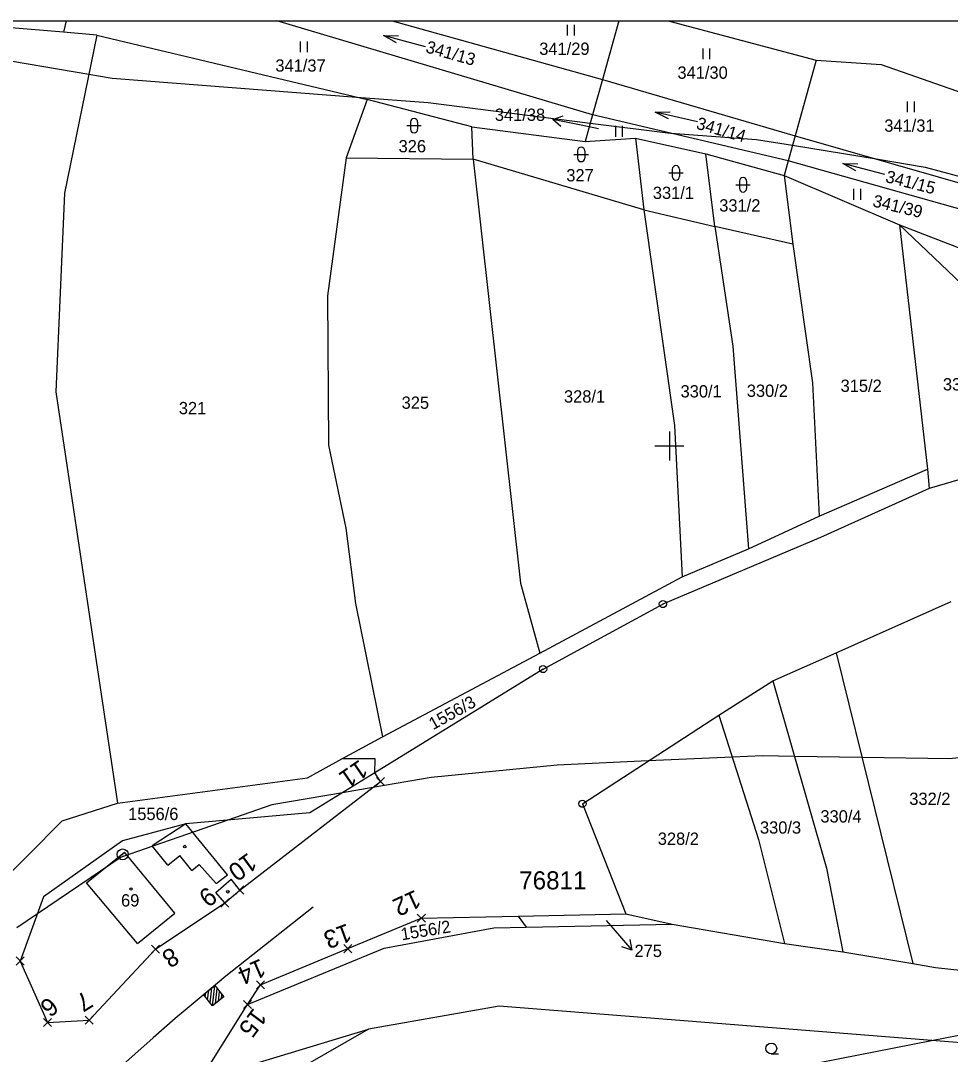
# Model space of a CAD drawing. Extents: x -756640 to -756220, y -1116031 to -1115741.
# Drawn here: x -756489.7 to -756361.1, y -1115884.2 to -1115741.2 of the extents above; entities that cross this region are included whole.
import ezdxf

# ---------------------------------------------------------------- set-up
doc = ezdxf.new("R2010")
doc.units = 0
for name, color, linetype in [('BPEJ', 7, 'Continuous'), ('GD_Starý stav', 7, 'Continuous'), ('Groma (60)', 7, 'Continuous'), ('Katastr_HRANICE DRÁHY', 7, 'Continuous'), ('Katastr_Hranice parcel', 7, 'Continuous'), ('Katastr_Parcelní čísla', 7, 'Continuous'), ('Katastr_Slučkované čáry', 7, 'Continuous'), ('Katastr_Značky kultur', 7, 'Continuous'), ('čtvercová síť', 7, 'Continuous')]:
    doc.layers.add(name, color=color, linetype=linetype)

# ---------------------------------------------------------------- blocks, each defined once
blk = doc.blocks.new('POINT_DISPLAY')
for p, q in [((-0.56, -0.56), (0.56, 0.56)), ((-0.56, 0.56), (0.56, -0.56))]:
    blk.add_line(p, q)
blk = doc.blocks.new('C691')
at = {"layer": 'čtvercová síť'}
for p, q in [((0, 0.5), (0, -0.5)), ((-0.5, 0), (0.5, 0))]:
    blk.add_line(p, q, dxfattribs=at)

msp = doc.modelspace()

# ---------------------------------------------------------------- linework, layer by layer
at = {"layer": 'BPEJ'}
for points in [[(-756499.55, -1115745.29), (-756480.27, -1115748.57), (-756477.06, -1115749.11), (-756443.26, -1115751.74), (-756433.35, -1115752.51), (-756410.94, -1115755.34), (-756399.83, -1115756.75), (-756399.8, -1115756.75), (-756387.95, -1115757.6), (-756382.96, -1115758.42), (-756371.38, -1115760.31), (-756364.61, -1115761.42), (-756355.88, -1115763.78)], [(-756355.89, -1115842.66), (-756361.22, -1115843.31), (-756373.35, -1115843.11), (-756382.69, -1115842.96), (-756387.1, -1115842.89), (-756391.28, -1115843.07), (-756402.93, -1115843.59), (-756415.53, -1115844.16), (-756432.93, -1115845.86), (-756441.01, -1115847.26), (-756445.2, -1115847.98), (-756454.99, -1115849.67), (-756461.04, -1115851.77), (-756475.79, -1115856.89), (-756487.39, -1115864.74), (-756490.21, -1115866.65)], [(-756381.59, -1115885.74), (-756363.76, -1115882.25), (-756359.95, -1115881.5), (-756342.55, -1115877.68), (-756332.79, -1115876.83)]]:
    msp.add_lwpolyline(points, dxfattribs=at)
at = {"layer": 'Defpoints'}
msp.add_line((-756640.13, -1115741.18), (-756220.13, -1115741.18), dxfattribs=at)
at = {"layer": 'GD_Starý stav'}
for p, q in [((-756449.25, -1115863.83), (-756461.35, -1115873.36)), ((-756461.35, -1115873.36), (-756463.65, -1115875.28)), ((-756463.65, -1115875.28), (-756468.32, -1115879.23)), ((-756463.52, -1115877.05), (-756463.28, -1115874.98)), ((-756463.19, -1115877.47), (-756462.86, -1115874.66)), ((-756462.78, -1115877.14), (-756462.53, -1115875.07)), ((-756464.18, -1115876.22), (-756464.11, -1115875.64)), ((-756463.85, -1115876.63), (-756463.69, -1115875.31)), ((-756462.36, -1115876.81), (-756462.2, -1115875.49)), ((-756461.94, -1115876.48), (-756461.88, -1115875.91)), ((-756468.32, -1115879.23), (-756471.39, -1115881.91)), ((-756471.39, -1115881.91), (-756475.58, -1115885.63))]:
    msp.add_line(p, q, dxfattribs=at)
msp.add_lwpolyline([(-756464.43, -1115875.9), (-756462.86, -1115874.66), (-756461.62, -1115876.23), (-756463.19, -1115877.47)], close=True, dxfattribs=at)
at = {"layer": 'Katastr_HRANICE DRÁHY'}
for points in [[(-756349.55, -1115801.67), (-756364.06, -1115805.89)], [(-756364.06, -1115805.89), (-756379.08, -1115812.68)], [(-756379.08, -1115812.68), (-756400.89, -1115821.88)], [(-756417.46, -1115830.87), (-756400.89, -1115821.88)], [(-756376.92, -1115828.62), (-756361.05, -1115821.51)], [(-756385.69, -1115832.48), (-756376.92, -1115828.62)], [(-756417.46, -1115830.87), (-756440.74, -1115845.23)], [(-756393.14, -1115837.23), (-756385.69, -1115832.48)], [(-756412.02, -1115849.5), (-756393.14, -1115837.23)], [(-756439.93, -1115846.42), (-756440.74, -1115845.23)], [(-756459.39, -1115861.44), (-756439.93, -1115846.42)], [(-756412.02, -1115849.5), (-756406.03, -1115864.73)], [(-756461.48, -1115863.23), (-756459.39, -1115861.44)], [(-756471.07, -1115869.62), (-756461.48, -1115863.23)], [(-756434.3, -1115865.34), (-756420.92, -1115865.05)], [(-756420.92, -1115865.05), (-756406.03, -1115864.73)], [(-756444.45, -1115869.55), (-756434.3, -1115865.34)], [(-756456.53, -1115874.56), (-756444.45, -1115869.55)], [(-756480.23, -1115879.43), (-756471.07, -1115869.62)], [(-756489.77, -1115871.26), (-756485.99, -1115879.76)], [(-756458.35, -1115877.27), (-756456.53, -1115874.56)], [(-756464.9, -1115887.76), (-756458.35, -1115877.27)], [(-756485.99, -1115879.76), (-756480.23, -1115879.43)]]:
    msp.add_lwpolyline(points, dxfattribs=at)
at = {"layer": 'Katastr_Hranice parcel'}
for points in [[(-756483.77, -1115742.78), (-756491, -1115742.18)], [(-756483.42, -1115741.18), (-756483.77, -1115742.78)], [(-756410.63, -1115754.22), (-756454.3, -1115741.18)], [(-756438.33, -1115741.18), (-756409.26, -1115749.32)], [(-756406.99, -1115741.18), (-756409.26, -1115749.32)], [(-756400.17, -1115741.18), (-756379.7, -1115746.62)], [(-756479.17, -1115743.17), (-756483.77, -1115742.78)], [(-756479.17, -1115743.17), (-756483.65, -1115765.05)], [(-756479.17, -1115743.17), (-756441.78, -1115752.09)], [(-756379.7, -1115746.62), (-756382.59, -1115757.09)], [(-756379.7, -1115746.62), (-756370.72, -1115747.22)], [(-756370.72, -1115747.22), (-756351.86, -1115753.85)], [(-756409.26, -1115749.32), (-756410.63, -1115754.22)], [(-756409.26, -1115749.32), (-756382.59, -1115757.09)], [(-756441.78, -1115752.09), (-756444.69, -1115760.15)], [(-756427.31, -1115755.86), (-756441.78, -1115752.09)], [(-756410.63, -1115754.22), (-756411.66, -1115757.9)], [(-756383.55, -1115760.55), (-756410.63, -1115754.22)], [(-756427.12, -1115760.35), (-756427.31, -1115755.86)], [(-756427.31, -1115755.86), (-756411.66, -1115757.9)], [(-756411.66, -1115757.9), (-756404.66, -1115757.44)], [(-756404.66, -1115757.44), (-756394.95, -1115759.62)], [(-756404.66, -1115757.44), (-756403.54, -1115767.35)], [(-756382.59, -1115757.09), (-756383.55, -1115760.55)], [(-756382.59, -1115757.09), (-756356.23, -1115764.66)], [(-756444.69, -1115760.15), (-756447.25, -1115779.26)], [(-756444.69, -1115760.15), (-756427.12, -1115760.35)], [(-756403.54, -1115767.35), (-756427.12, -1115760.35)], [(-756427.12, -1115760.35), (-756420.59, -1115819.01)], [(-756394.95, -1115759.62), (-756384.11, -1115762.59)], [(-756393.69, -1115769.66), (-756394.95, -1115759.62)], [(-756383.55, -1115760.55), (-756384.11, -1115762.59)], [(-756357.53, -1115767.92), (-756383.55, -1115760.55)], [(-756384.11, -1115762.59), (-756382.93, -1115772.11)], [(-756384.11, -1115762.59), (-756368.19, -1115769.4)], [(-756483.65, -1115765.05), (-756484.84, -1115792.54)], [(-756403.54, -1115767.35), (-756393.69, -1115769.66)], [(-756403.54, -1115767.35), (-756399.29, -1115797.17)], [(-756368.19, -1115769.4), (-756358.61, -1115778.51)], [(-756368.19, -1115769.4), (-756359.47, -1115772.77)], [(-756368.19, -1115769.4), (-756364.32, -1115803.23)], [(-756382.93, -1115772.11), (-756393.69, -1115769.66)], [(-756393.69, -1115769.66), (-756391.23, -1115786.2)], [(-756382.93, -1115772.11), (-756380.19, -1115791.29)], [(-756447.25, -1115779.26), (-756447.12, -1115799.88)], [(-756391.23, -1115786.2), (-756389.05, -1115814.22)], [(-756380.19, -1115791.29), (-756379.27, -1115809.72)], [(-756484.84, -1115792.54), (-756476.32, -1115849.42)], [(-756399.29, -1115797.17), (-756398.23, -1115818.12)], [(-756447.12, -1115799.88), (-756444.74, -1115811.37)], [(-756379.27, -1115809.72), (-756364.32, -1115803.23)], [(-756364.32, -1115803.23), (-756364.06, -1115805.89)], [(-756389.05, -1115814.22), (-756379.27, -1115809.72)], [(-756444.74, -1115811.37), (-756443.42, -1115821.82)], [(-756398.23, -1115818.12), (-756389.05, -1115814.22)], [(-756420.59, -1115819.01), (-756417.92, -1115828.69)], [(-756417.92, -1115828.69), (-756398.23, -1115818.12)], [(-756443.42, -1115821.82), (-756439.65, -1115840.25)], [(-756439.65, -1115840.25), (-756417.92, -1115828.69)], [(-756376.92, -1115828.62), (-756366.32, -1115871.62)], [(-756385.69, -1115832.48), (-756378.27, -1115858.42)], [(-756393.14, -1115837.23), (-756387.65, -1115854.44)], [(-756445.28, -1115843.31), (-756439.65, -1115840.25)], [(-756450.06, -1115845.91), (-756445.28, -1115843.31)], [(-756440.69, -1115843.31), (-756445.28, -1115843.31)], [(-756440.74, -1115845.23), (-756440.69, -1115843.31)], [(-756440.74, -1115845.23), (-756449.72, -1115850.77)], [(-756476.32, -1115849.42), (-756450.06, -1115845.91)], [(-756483.98, -1115851.89), (-756476.32, -1115849.42)], [(-756449.72, -1115850.77), (-756466.87, -1115852.29)], [(-756493.49, -1115861.47), (-756483.98, -1115851.89)], [(-756466.87, -1115852.29), (-756475.62, -1115854.64)], [(-756475.62, -1115854.64), (-756486.53, -1115862.38)], [(-756387.65, -1115854.44), (-756384.07, -1115868.86)], [(-756378.27, -1115858.42), (-756375.99, -1115870.01)], [(-756486.53, -1115862.38), (-756489.77, -1115871.26)], [(-756420.92, -1115865.05), (-756419.79, -1115866.57)], [(-756406.03, -1115864.73), (-756399.6, -1115866.17)], [(-756439.44, -1115869.47), (-756424.26, -1115866.66)], [(-756424.26, -1115866.66), (-756419.79, -1115866.57)], [(-756419.79, -1115866.57), (-756399.6, -1115866.17)], [(-756399.6, -1115866.17), (-756384.07, -1115868.86)], [(-756458.35, -1115877.27), (-756439.44, -1115869.47)], [(-756384.07, -1115868.86), (-756375.99, -1115870.01)], [(-756375.99, -1115870.01), (-756366.32, -1115871.62)], [(-756366.32, -1115871.62), (-756363.21, -1115872.14)], [(-756363.21, -1115872.14), (-756348.29, -1115873.78)], [(-756423.52, -1115877.5), (-756441.61, -1115880.7)], [(-756323.04, -1115885.48), (-756423.52, -1115877.5)], [(-756464.9, -1115887.76), (-756441.61, -1115880.7)], [(-756441.61, -1115880.7), (-756453.8, -1115887.71)]]:
    msp.add_lwpolyline(points, dxfattribs=at)
at = {"layer": 'Katastr_Parcelní čísla'}
for p, q in [((-756414.99, -1115755.83), (-756416.11, -1115754.84)), ((-756409.79, -1115756.12), (-756412.19, -1115755.63)), ((-756408.75, -1115865.64), (-756407.79, -1115866.75)), ((-756405.45, -1115868.3), (-756405.17, -1115869.77))]:
    msp.add_line(p, q, dxfattribs=at)
for points in [[(-756412.19, -1115755.63), (-756416.11, -1115754.84), (-756414.69, -1115754.36)], [(-756407.79, -1115866.75), (-756405.17, -1115869.77), (-756406.58, -1115869.28)]]:
    msp.add_lwpolyline(points, dxfattribs=at)
at = {"layer": 'Katastr_Slučkované čáry'}
for points in [[(-756466.87, -1115852.29), (-756471.5, -1115855.31)], [(-756461.12, -1115859.32), (-756466.87, -1115852.29)], [(-756480.62, -1115860.45), (-756475.36, -1115856.19)], [(-756474.48, -1115857.26), (-756475.36, -1115856.19)], [(-756469.37, -1115857.99), (-756471.5, -1115855.31)], [(-756469.37, -1115857.99), (-756467.7, -1115856.66)], [(-756466.04, -1115858.75), (-756467.7, -1115856.66)], [(-756468.39, -1115864.63), (-756474.48, -1115857.26)], [(-756466.04, -1115858.75), (-756465.01, -1115857.93)], [(-756462.69, -1115860.54), (-756465.01, -1115857.93)], [(-756462.69, -1115860.54), (-756461.12, -1115859.32)], [(-756473.55, -1115868.86), (-756480.62, -1115860.45)], [(-756462.73, -1115861.77), (-756460.61, -1115859.95)], [(-756459.39, -1115861.44), (-756460.61, -1115859.95)], [(-756461.48, -1115863.23), (-756462.73, -1115861.77)], [(-756473.55, -1115868.86), (-756468.39, -1115864.63)]]:
    msp.add_lwpolyline(points, dxfattribs=at)
at = {"layer": 'Katastr_Značky kultur'}
for p, q in [((-756414.11, -1115741.75), (-756414.11, -1115743.25)), ((-756413.11, -1115743.25), (-756413.11, -1115741.75)), ((-756433.73, -1115744.78), (-756439.53, -1115743.25)), ((-756451.03, -1115744.04), (-756451.03, -1115745.54)), ((-756450.03, -1115745.54), (-756450.03, -1115744.04)), ((-756395.38, -1115745.01), (-756395.38, -1115746.51)), ((-756394.38, -1115746.51), (-756394.38, -1115745.01)), ((-756367.1, -1115752.34), (-756367.1, -1115753.84)), ((-756366.1, -1115753.84), (-756366.1, -1115752.34)), ((-756396.11, -1115755.15), (-756401.97, -1115753.83)), ((-756436.31, -1115755.7), (-756434.31, -1115755.7)), ((-756435.81, -1115755.2), (-756435.81, -1115756.2)), ((-756434.81, -1115755.2), (-756434.81, -1115756.2)), ((-756407.47, -1115755.74), (-756407.47, -1115757.24)), ((-756406.47, -1115757.24), (-756406.47, -1115755.74)), ((-756412.69, -1115759.18), (-756412.69, -1115760.18)), ((-756411.69, -1115759.18), (-756411.69, -1115760.18)), ((-756413.19, -1115759.68), (-756411.19, -1115759.68)), ((-756400.09, -1115762.23), (-756398.09, -1115762.23)), ((-756399.59, -1115761.73), (-756399.59, -1115762.73)), ((-756398.59, -1115761.73), (-756398.59, -1115762.73)), ((-756370.2, -1115762.45), (-756376, -1115760.95)), ((-756390.31, -1115763.38), (-756390.31, -1115764.38)), ((-756389.31, -1115763.38), (-756389.31, -1115764.38)), ((-756390.81, -1115763.88), (-756388.81, -1115763.88)), ((-756374.53, -1115764.44), (-756374.53, -1115765.94)), ((-756373.53, -1115765.94), (-756373.53, -1115764.44)), ((-756400.94, -1115821.88), (-756400.84, -1115821.88)), ((-756417.51, -1115830.87), (-756417.41, -1115830.87)), ((-756412.07, -1115849.5), (-756411.97, -1115849.5)), ((-756475.65, -1115856.52), (-756475.55, -1115856.52)), ((-756385.91, -1115884.11), (-756384.91, -1115884.11))]:
    msp.add_line(p, q, dxfattribs=at)
for points in [[(-756437.73, -1115744.24), (-756439.53, -1115743.25), (-756437.47, -1115743.27)], [(-756400.13, -1115754.76), (-756401.97, -1115753.83), (-756399.91, -1115753.78)], [(-756374.19, -1115761.93), (-756376, -1115760.95), (-756373.94, -1115760.97)]]:
    msp.add_lwpolyline(points, dxfattribs=at)
for centre, radius in [((-756400.89, -1115821.88), 0.499), ((-756417.46, -1115830.87), 0.499), ((-756412.02, -1115849.5), 0.499), ((-756467.01, -1115855.43), 0.175), ((-756475.6, -1115856.52), 0.756), ((-756474.45, -1115861.3), 0.175), ((-756461.06, -1115861.68), 0.175), ((-756385.91, -1115883.36), 0.75)]:
    msp.add_circle(centre, radius, dxfattribs=at)
for centre, start, end in [((-756435.31, -1115755.2), 0, 180), ((-756435.31, -1115756.2), 180, 0), ((-756412.19, -1115759.18), 0, 180), ((-756412.19, -1115760.18), 180, 0), ((-756399.09, -1115761.73), 0, 180), ((-756399.09, -1115762.73), 180, 0), ((-756389.81, -1115763.38), 0, 180), ((-756389.81, -1115764.38), 180, 0)]:
    msp.add_arc(centre, 0.5, start, end, dxfattribs=at)

# ---------------------------------------------------------------- block references
at = {"layer": 'Groma (60)', "rotation": 180}
for p in [(-756439.93, -1115846.42), (-756459.39, -1115861.44), (-756461.48, -1115863.23), (-756434.3, -1115865.34), (-756471.07, -1115869.62), (-756444.45, -1115869.55), (-756489.77, -1115871.26), (-756456.53, -1115874.56), (-756458.35, -1115877.27), (-756485.99, -1115879.76), (-756480.23, -1115879.43)]:
    msp.add_blockref('POINT_DISPLAY', p, dxfattribs=at)
at = {"layer": 'čtvercová síť', "xscale": 4, "yscale": 4}
msp.add_blockref('C691', (-756400, -1115800), dxfattribs=at)

# ---------------------------------------------------------------- texts
at = {"layer": 'BPEJ'}
msp.add_text('76811', height=2.5, dxfattribs=at).set_placement((-756420.76, -1115861.35))
at = {"layer": 'Groma (60)'}
for s, rotation, p in [('11', 214.5709, (-756442.83, -1115843.31)), ('10', 216.1965, (-756458.24, -1115856.18)), ('9', 217.9446, (-756463.83, -1115860.84)), ('12', 204.5957, (-756435.11, -1115861.35)), ('13', 200.1813, (-756444.54, -1115866.03)), ('8', 211.2053, (-756468.81, -1115869.25)), ('14', 203.2361, (-756456.51, -1115870.88)), ('6', 219.9246, (-756485.81, -1115876.08)), ('7', 211.9347, (-756480.79, -1115875.31)), ('15', 233.3127, (-756457.47, -1115877.61))]:
    msp.add_text(s, height=2.5, rotation=rotation, dxfattribs=at).set_placement(p)
at = {"layer": 'Katastr_Parcelní čísla'}
for s, rotation, p in [('341/13', 344.1959, (-756433.8, -1115745.54)), ('341/14', 343.9074, (-756396.39, -1115756.1)), ('341/15', 345.681, (-756370.21, -1115763.49)), ('341/39', 346.4088, (-756371.99, -1115766.86)), ('1556/3', 29.2299, (-756432.66, -1115839.34)), ('1556/2', 9.3485, (-756436.99, -1115868.41))]:
    msp.add_text(s, height=1.7, rotation=rotation, dxfattribs=at).set_placement(p)
for s, p in [('341/29', (-756417.99, -1115745.91)), ('341/37', (-756454.48, -1115748.23)), ('341/30', (-756398.88, -1115749.21)), ('341/38', (-756424.13, -1115755.04)), ('341/31', (-756370.28, -1115756.54)), ('326', (-756437.44, -1115759.39)), ('327', (-756414.25, -1115763.41)), ('331/1', (-756402.28, -1115765.84)), ('331/2', (-756393.1, -1115767.58)), ('315/2', (-756376.32, -1115792.53)), ('333/1', (-756362.17, -1115792.33)), ('328/1', (-756414.57, -1115794.01)), ('330/1', (-756398.45, -1115793.3)), ('330/2', (-756389.29, -1115793.22)), ('325', (-756437.02, -1115794.87)), ('321', (-756467.83, -1115795.62)), ('332/2', (-756366.82, -1115849.67)), ('1556/6', (-756474.84, -1115851.76)), ('330/4', (-756379.11, -1115852.1)), ('330/3', (-756387.47, -1115853.64)), ('328/2', (-756401.6, -1115855.19)), ('69', (-756475.82, -1115863.72)), ('275', (-756404.82, -1115870.71))]:
    msp.add_text(s, height=1.7, dxfattribs=at).set_placement(p)

doc.saveas('drawing.dxf')
